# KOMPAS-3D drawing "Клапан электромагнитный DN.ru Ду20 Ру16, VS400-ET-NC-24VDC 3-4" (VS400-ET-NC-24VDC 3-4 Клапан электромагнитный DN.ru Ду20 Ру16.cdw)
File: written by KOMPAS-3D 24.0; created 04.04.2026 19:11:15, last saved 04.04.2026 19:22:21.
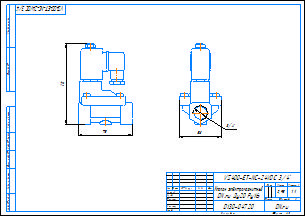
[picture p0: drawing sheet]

Document properties: c3d_UniqueCompID: ef56311e-7521-43dc-8291-0e6108b3d81d; Обозначение: VS400-ET-NC-220VAC 1-2; Наименование: Клапан электромагнитный DN.ru Ду15 Ру16; Автор: artio; Класс точности: c; Знак неуказанной шероховатости: Шероховатость не задана; Рассекать на разрезах: Да; c3d_UniqueCompID: ef56311e-7521-43dc-8291-0e6108b3d81d; Обозначение: VS400-ET-NC-220VAC 3-4; Наименование: Клапан электромагнитный DN.ru Ду20 Ру16; Автор: artio; Класс точности: c; Знак неуказанной шероховатости: Шероховатость не задана; Рассекать на разрезах: Да; c3d_UniqueCompID: ef56311e-7521-43dc-8291-0e6108b3d81d; Обозначение: VS400-ET-NC-220VAC 3-8; Наименование: Клапан электромагнитный DN.ru Ду10 Ру16; Автор: artio; Класс точности: c; Знак неуказанной шероховатости: Шероховатость не задана; Рассекать на разрезах: Да; Автор: artio; Форматы листов документа: A3; Полное имя файла: VS400-ET-NC-24VDC 3-4 Клапан электромагнитный DN.ru Ду20 Ру16.m3d; Масса: 0.954; Наименование: Клапан электромагнитный DN.ru Ду20 Ру16; Количество листов документа: 1; Примечание: D130-04719

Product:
- Body: Тело 1  | qty 1
    Масса: 1.210539
- Part/product: Клапан электромагнитный DN.ru Ду20 Ру16  | designation VS400-ET-NC-24VDC 3-4
    Масса: 0.954
    Раздел спецификации: Прочие изделия
    Примечание: D130-04719
    additional columns: ef56311e-7521-43dc-8291-0e6108b3d81d; VS400-ET-NC-220VAC 3-4; artio; c; Шероховатость не задана; Да

Views: Вид 1, Спереди, Проекционный вид 2
Referenced files in C:\Users\artio\OneDrive\Рабочий стол\Клапан электромагнитный DN.ru\VS400-ET-NC\VS400-ET-NC-24VDC\: VS400-ET-NC-24VDC 3-8 Клапан электромагнитный DN.ru Ду10 Ру16.m3d, VS400-ET-NC-24VDC 3-4 Клапан электромагнитный DN.ru Ду20 Ру16.m3d
Referenced files in C:\Users\artio\OneDrive\Рабочий стол\Клапан электромагнитный DN.ru\VS400-ET-NC\: VS400-ET-NC-24VDC 3-8 Клапан электромагнитный DN.ru Ду10 Ру16.cdw
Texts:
  VS400-ET-NC-24VDC 3-4
  Клапан электромагнитный
  DN.ru Ду20 Ру16
  VS400-ET-NC-24VDC 3/4"
  VS400-ET-NC-24VDC 3/4"-
  Клапан электромагнитный DN.ru Ду20 Ру16
  VS400-ET-NC-24VDC 3-4 Клапан электромагнитный DN.ru Ду20 Ру16
Dimensions and other numbers on the sheet: 0; 3; 2; 4; 58; 3/4"; 75; 112; 1:1; 1; 0,95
